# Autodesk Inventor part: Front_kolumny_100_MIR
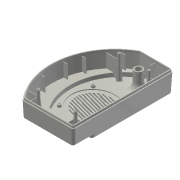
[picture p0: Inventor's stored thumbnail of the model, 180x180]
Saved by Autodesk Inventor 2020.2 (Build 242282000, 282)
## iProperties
Created: 2010-12
Part Number: Front_kolumny_100_MIR
Document SubType Name: Modeling
Designer: F.Stasiak
Density: 1 g/cm^3
Material: Ogólny
Appearance: Gładkie — w kolorze kości słoniowej
Manager: www.cadconsulting.pl
Company: Fabian Stasiak CAD Consulting
Author: F.Stasiak
Subject: Zbiór ćwiczeń. Autodesk Inventor 2020. Kurs podstawowy
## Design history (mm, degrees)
derived "Front_kolumny_100.ipt"
  sketch "Szkic1"
    geometry: L1 (0, 0)-(0, 200) reference; L2 (0, 200)-(65, 200) reference; L3 (0, 0)-(100, 0) reference; A1 r 130 centre (2.514, 86.002) between (100, 0) and (65, 200) reference
  sketch "Szkic3"
    geometry: L1 (0, 0)-(100, 0) reference; L2 (0, 200)-(0, 0) reference; L3 (65, 200)-(0, 200) reference; L4 (0, 38.775)-(90, 38.775) reference; A1 r 130 centre (2.514, 86.002) between (100, 0) and (65, 200) reference; A2 r 110 centre (0, 102.02) between (90, 38.775) and (50, 200) reference; 1 further point
  sketch "Szkic2"
    geometry: A1 r 900 centre (-62.935, -861.801) between (4.9, 35.639) and (-144.257, 34.518) reference; 1 further point
  sketch "Szkic5"
    geometry: L1 (-40, 0)-(-40, 38) reference; L2 (0, 0)-(-65, 0) reference; L3 (-52.399, 38)-(-109.651, 38) reference; L4 (-46, 0)-(-46, 20) reference; L5 (-52.399, 38)-(-1.659, 38) reference; L6 (-57.282, 38)-(-40, 38) reference; L7 (-46, 0)-(-40, 0) reference; A1 r 20 centre (-66, 20) between (-46, 20) and (-57.282, 38) reference; 1 further point
  sketch "Szkic7"
    geometry: L1 (-3.503, 5.002)-(-3.503, 194.998) reference; L2 (-5.002, 196.497)-(-63.706, 196.497) reference; L3 (-97.716, 3.503)-(-5.002, 3.503) reference; L4 (-34.354, 196.497)-(-34.354, 188.497) reference; L5 (-3.503, 181.497)-(-11.503, 181.497) reference; L6 (-85.473, 181.497)-(-77.473, 181.497) reference; L7 (-3.503, 166.497)-(-15.503, 166.497) reference; L8 (-100.095, 166.497)-(-75.095, 166.497) reference; L9 (-3.503, 100)-(-9.503, 100) reference; L10 (-127.031, 108.292)-(-119.031, 108.292) reference; L11 (-3.503, 136.497)-(-11.503, 136.497) reference; L12 (-118.495, 136.497)-(-110.495, 136.497) reference; L13 (-3.503, 23.503)-(-18.503, 23.503) reference; L14 (-112.492, 23.503)-(-92.492, 23.503) reference; L15 (-3.503, 63.503)-(-11.503, 63.503) reference; L16 (-126.993, 63.503)-(-118.993, 63.503) reference; L17 (-18.503, 3.503)-(-18.503, 23.503) reference; L18 (-92.492, 23.503)-(-92.492, 3.503) reference; A1 r 126.497 centre (-2.514, 86.002) between (-64.439, 196.305) and (-98.857, 4.031) reference; 1 further point
  sketch "SZKIC KRATKI"
    geometry: L1 (0, 4.995)-(0, 195.005) reference; L2 (97.719, 0)-(4.995, 0) reference; L3 (96.052, 106)-(13.948, 84) reference; L4 (60.5, 74.474)-(49.5, 115.526) reference; L5 (94.758, 110.829)-(12.654, 88.83) reference; L6 (93.464, 115.659)-(11.36, 93.659) reference; L7 (92.17, 120.489)-(10.066, 98.489) reference; L8 (90.875, 125.318)-(8.772, 103.319) reference; L9 (89.581, 130.148)-(7.478, 108.148) reference; L10 (88.287, 134.978)-(6.184, 112.978) reference; L11 (97.346, 101.17)-(15.242, 79.171) reference; L12 (96.052, 106)-(13.948, 84) reference; L13 (94.758, 110.829)-(12.654, 88.83) reference; L14 (93.464, 115.659)-(11.36, 93.659) reference; L15 (92.17, 120.489)-(10.066, 98.489) reference; L16 (90.875, 125.318)-(8.772, 103.319) reference; L17 (89.581, 130.148)-(7.478, 108.148) reference; L18 (98.64, 96.341)-(16.536, 74.341) reference; L19 (97.346, 101.17)-(15.242, 79.171) reference; L20 (96.052, 106)-(13.948, 84) reference; L21 (94.758, 110.829)-(12.654, 88.83) reference; L22 (93.464, 115.659)-(11.36, 93.659) reference; L23 (92.17, 120.489)-(10.066, 98.489) reference; L24 (90.875, 125.318)-(8.772, 103.319) reference; L25 (99.934, 91.511)-(17.83, 69.511) reference; L26 (98.64, 96.341)-(16.536, 74.341) reference; L27 (97.346, 101.17)-(15.242, 79.171) reference; L28 (96.052, 106)-(13.948, 84) reference; L29 (94.758, 110.829)-(12.654, 88.83) reference; L30 (93.464, 115.659)-(11.36, 93.659) reference; L31 (92.17, 120.489)-(10.066, 98.489) reference; L32 (101.228, 86.681)-(19.125, 64.682) reference; L33 (99.934, 91.511)-(17.83, 69.511) reference; L34 (98.64, 96.341)-(16.536, 74.341) reference; L35 (97.346, 101.17)-(15.242, 79.171) reference; L36 (96.052, 106)-(13.948, 84) reference; L37 (94.758, 110.829)-(12.654, 88.83) reference; L38 (93.464, 115.659)-(11.36, 93.659) reference; L39 (102.522, 81.852)-(20.419, 59.852) reference; L40 (101.228, 86.681)-(19.125, 64.682) reference; L41 (99.934, 91.511)-(17.83, 69.511) reference; L42 (98.64, 96.341)-(16.536, 74.341) reference; L43 (97.346, 101.17)-(15.242, 79.171) reference; L44 (96.052, 106)-(13.948, 84) reference; L45 (94.758, 110.829)-(12.654, 88.83) reference; L46 (103.816, 77.022)-(21.713, 55.022) reference; L47 (102.522, 81.852)-(20.419, 59.852) reference; L48 (101.228, 86.681)-(19.125, 64.682) reference; L49 (99.934, 91.511)-(17.83, 69.511) reference; L50 (98.64, 96.341)-(16.536, 74.341) reference; L51 (97.346, 101.17)-(15.242, 79.171) reference; L52 (96.052, 106)-(13.948, 84) reference; L53 (86.993, 139.807)-(4.889, 117.808) reference; L54 (88.287, 134.978)-(6.184, 112.978) reference; L55 (89.581, 130.148)-(7.478, 108.148) reference; L56 (90.875, 125.318)-(8.772, 103.319) reference; L57 (92.17, 120.489)-(10.066, 98.489) reference; L58 (93.464, 115.659)-(11.36, 93.659) reference; L59 (94.758, 110.829)-(12.654, 88.83) reference; L60 (105.111, 72.192)-(23.007, 50.193) reference; L61 (103.816, 77.022)-(21.713, 55.022) reference; L62 (102.522, 81.852)-(20.419, 59.852) reference; L63 (101.228, 86.681)-(19.125, 64.682) reference; L64 (99.934, 91.511)-(17.83, 69.511) reference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; C1 r 40 at (55, 95) reference; A1 r 42.5 centre (55, 95) between (96.052, 106) and (13.948, 84) reference; 65 further points
    constraints: 2 other
  sketch "SZKIC MONTAŻU GŁOŚNIKA"
    geometry: L1 (21.459, 128.541)-(88.541, 128.541) reference; L2 (88.541, 128.541)-(88.541, 61.459) reference; L3 (88.541, 61.459)-(21.459, 61.459) reference; L4 (21.459, 61.459)-(21.459, 128.541) reference; C1 r 42.5 at (55, 95) reference; A1 r 47.435 centre (55, 95) between (21.459, 128.541) and (88.541, 128.541) reference; 4 further points
  sketch "SZKIC KOMINKÓW MONTAŻOWYCH"
    geometry: L1 (-75.095, 166.997)-(-75.095, 165.997) reference; L2 (-15.503, 165.997)-(-15.503, 166.997) reference; L3 (-3.503, 23.003)-(-18.003, 23.003) reference; L4 (-19.003, 3.503)-(-19.003, 24.003) reference; L5 (-18.003, 23.003)-(-19.003, 24.003) reference; L6 (-92.992, 23.003)-(-112.207, 23.003) reference; L7 (-91.992, 24.003)-(-91.992, 3.503) reference; L8 (-92.992, 23.003)-(-91.992, 24.003) reference; 5 further points
  node "Płaszczyzna konstrukcyjna1"
  node "Płaszczyzna konstrukcyjna4"
  node "Płaszczyzna konstrukcyjna5"
sketch "Szkic11"
  geometry: L1 (-4.995, 2.997)-(-4.995, 40.462) reference; L2 (90.929, -1.998)-(0, -1.998) reference; C1 r 4 at (30.005, 16.002); 1 further point
  constraints: 1 centre point
  dimensions: "d1" = 8 diameter of C1; "d2" = 35 distance from line of L1 C1.centre; "d3" = 18 distance from line of L2 C1.centre
extrude "Wyciągnięcie proste1" cut sketch "Szkic11" extent not by distance; stored distance "d4" = 10; taper "d5" = 0 deg
pattern_linear "Szyk prostokątny1" dims "d8" = 20
feature "Bryła1::Front_kolumny_100.ipt" dims "d0" = 10
node "Płaszczyzna konstrukcyjna2"
feature "Srf1::Front_kolumny_100.ipt"
body "Srf1"
tag "Bryła wyprowadzona1"
node "Bryła1"
